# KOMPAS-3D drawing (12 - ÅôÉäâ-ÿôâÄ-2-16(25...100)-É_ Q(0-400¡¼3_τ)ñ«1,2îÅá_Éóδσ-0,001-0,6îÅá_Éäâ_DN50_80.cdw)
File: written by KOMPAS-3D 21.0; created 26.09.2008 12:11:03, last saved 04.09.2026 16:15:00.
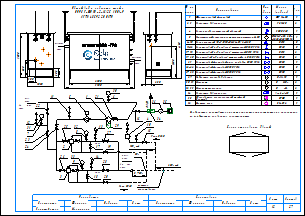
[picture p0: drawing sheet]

Sheets 1-2: A3, landscape

Document properties: Наименование: Макро:21; Автор: RaskoAdmin; Форматы листов документа: 2xA3; Полное имя файла: \\ur38nt01\Departments\КТО\КБ ПУРДГ\Заявки\Прайс-лист на типовые шкафы ГРПШ\ПУРДГ_стандарт_30_04_2026\ПУРДГ с РДГ(Н, В)\ПУРДГ-ШУГО-2-16(25...100)-Р_ Q(0-400нм3_ч)до1,2МПа_Рвых-0,001-0,6МПа_РДГ_DN50_80.cdw

Title block, sheet 1: Наименование: Пункт учета газа / ПУГ-Ш-400-Р / ЛГТИ.485922.001ТУ; designation: ЛГТИ.03.4411141; sheet number: 1; Количество листов документа: 2; organisation: ООО "ЭЛЬСТЕР Газэлектроника"; Форматы листов документа: A3; stored path: C:\Рабочие документы\Компас\ПУГ\Схема.cdw; Разработал: Устинов; Проверил: Кошкин; Утвердил: Кошкин
Title block, sheet 2: sheet number: 2; stored path: D:\Рабочие документы\Заявки\ПУРДГ\ПУРДГ-ШУЭО-2-100-Р 4411220.cdw; designation, second copy: ЛГТИ.03.4411141-

Views: Вид 1, Вид 2
Referenced files: wcvoit.frw
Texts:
  Normal
  № на
  схеме
  Усл.
  обозн.
  Марка
  (модель)
  Кол.
  Фильтр газовый фланцевый
  ФГ 16-50
  Регулятор давления газа
  РДГ-50
  Клапан предохранительный сбросной
  КПС DN20
  Измерительный комплекс с ротационным счетчиком Ду50
  СГ-ЭК-Р-(0,2...2,0)-
  Кран кнопочный VE-РАСКО-НЗ-1,6-G1/2-М20
  DN15
  Кран шаровой "под приварку" штуцерный DN20 PN16
  DN20
  Кран шаровой "под приварку" штуцерный DN15 PN16
  Кран шаровой "под приварку" штуцерный п/п DN20 PN16
  Кран шаровой фланцевый с мех. приводом DN50 PN16
  Кран шаровой фланцевый DN50 PN16
  Кран шаровой фланцевый DN80 PN16
  DN50
  DN80
  Индикатор перепада давления
  Манометр
  Манометр-напоромер
  Обогреватель газогорелочный шкафной
  (Эльтон")
  Счетчик газа
  Delta 15
  0...     МПа
  0...     кПа
  Venio-A-15
  ОГШН
  BK-G1,6
  Общий вид и габариты шкафа
  ПУРДГ-ШУГО-2-16(25...100)-Р
  Выход газа
  Вход газа
  logo-rasko-ge.png
  DN 1
  местное
  сопротивление
  Римп DN20
  Выход
  газа
  Р=     кПа
  Вход
  Р=       МПа
  PDI
  Схема открывания дверей
  Предприятие изготовитель может заменять комплектующие на аналогичные,
  не ухудшающие заявленных характеристик.
  Должность
  Конструктор
  Фамилия
  Подпись
  Дата
  Согласовано
  Максимкин
  Лист
  Листов
  POLYLINE_STYLE_0.18_RGB_0_0_0
  POLYLINE_STYLE_0.50_RGB_0_0_0
  POLYLINE_STYLE_0.34_RGB_0_0_0
  PHANTOM_RGB_0_0_0_SC_1_THICK_0.18
  K5LT_THIN_RGB_0_0_0_THICK_0.18
  K5LT32769_RGB_0_0_0_THICK_0.18
  K5LT12_RGB_0_0_0_SC_1_THICK_0.18
  K5LT_DASHED_RGB_0_0_0_SC_1_THICK_0.18
  ACISOTGL_RGB_0_0_0_SC_0.8_THICK_0.25
  CONTINUOUS_RGB_0_127_31_THICK_0.3
  CONTINUOUS_RGB_0_0_255_THICK_0.35
  CONTINUOUS_RGB_255_0_0_THICK_0.35
  POLYLINE_STYLE_0.25_RGB_0_0_0
  CONTINUOUS_RGB_0_0_0_THICK_0.5
  POLYLINE_STYLE_0.35_RGB_0_0_255
  CONTINUOUS_RGB_0_0_0_THICK_0.4
  CONTINUOUS_RGB_0_0_0_THICK_0.35
  НЕВИДИМАЯ_RGB_0_0_0_SC_0.3_THICK_0.25
  СONTINUOUS_RGB_0_0_0_THICK_0.25
  ОСЕВАЯ2_RGB_248_153_30_SC_0.3_THICK_0.25
  Без оформления
Dimensions and other numbers on the sheet: 1; 2, 3; 2; 4; 5; 6-10; 11-16; 17, 18; 19, 20; 21; 22-26; 27, 28; 29; 30, 31; 32, 33; 34; 35; 36; 1500; 250; 300; 1050; 550; 305; 2800; 4130; 2000; 3100; 5,,,7DN 1; 7; 31; 12; 22; 23; 24; 11; 6; 30; 25; 32; 8; 13; 27; 19; 10; 15; 26; 33; 9; 3; 14; 28; 20; 17; 18; 16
